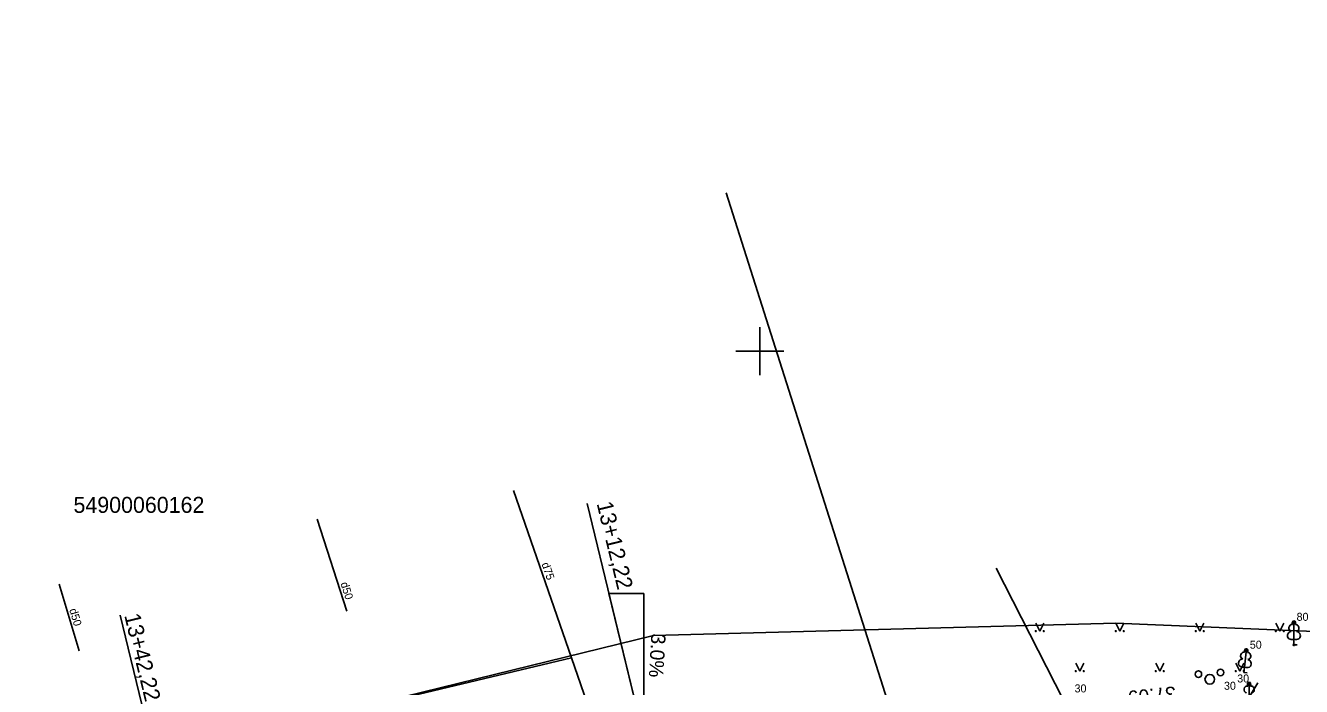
# Model space of a CAD drawing. Extents: x 469981 to 472086, y 246785 to 247785.
# Drawn here: x 470754.1 to 470833.9, y 247229 to 247270.3 of the extents above; entities that cross this region are included whole.
import ezdxf

# ---------------------------------------------------------------- set-up
doc = ezdxf.new("R2010")
doc.units = 0
for name, color, linetype in [('0_Koki_certami', 7, 'Continuous'), ('0_vertkals_cipari', 7, 'Continuous'), ('0_Virazjas', 7, 'Continuous'), ('DREN_VADP_####_####_#', 7, 'Continuous'), ('DREN_VADP_####_TKST_#', 7, 'Continuous'), ('DREN_VADP_KLKT_####_#', 7, 'Continuous'), ('DREN_VADP_KLKT_TKST_#', 7, 'Continuous'), ('GEOD_ELEM_####_####_#', 7, 'Continuous'), ('RAMI_UZMR_####_####_#', 7, 'Continuous'), ('RELJ_ELEM_####_####_#', 7, 'Continuous'), ('ROBZ_PROJ_####_####_#', 7, 'Continuous'), ('ROBZ_PROJ_####_TKST_#', 7, 'Continuous'), ('TERT_DIAM_####_TKST_#', 7, 'Continuous'), ('TERT_ELEM_####_####_#', 7, 'Continuous'), ('TERT_KOKR_####_####_#', 7, 'Continuous')]:
    doc.layers.add(name, color=color, linetype=linetype)

msp = doc.modelspace()

# ---------------------------------------------------------------- linework, layer by layer
at = {"layer": '0_Koki_certami'}
msp.add_line((470831.138, 247229.278), (470830.109, 247227.575), dxfattribs=at)
at = {"layer": '0_Virazjas'}
for p, q in [((470789.207, 247240.478), (470794.554, 247218.496)), ((470760.032, 247233.489), (470765.404, 247211.405))]:
    msp.add_line(p, q, dxfattribs=at)
msp.add_lwpolyline([(470792.75, 247234.859), (470790.575, 247234.855), (470792.763, 247225.859)], close=True, dxfattribs=at)
at = {"layer": 'DREN_VADP_####_####_#'}
for points in [[(470774.193, 247233.753), (470772.334, 247239.501)], [(470756.214, 247235.437), (470757.459, 247231.26)], [(470788.229, 247230.84), (470790.777, 247223.487), (470677.88, 247197.532)], [(470730.143, 247216.979), (470788.229, 247230.84)]]:
    msp.add_lwpolyline(points, dxfattribs=at)
at = {"layer": 'DREN_VADP_KLKT_####_#'}
msp.add_lwpolyline([(470788.229, 247230.84), (470784.609, 247241.284)], dxfattribs=at)
at = {"layer": 'GEOD_ELEM_####_####_#'}
for p, q in [((470800, 247251.5), (470800, 247250)), ((470798.5, 247250), (470800, 247250)), ((470800, 247250), (470800, 247248.5)), ((470800, 247250), (470801.5, 247250))]:
    msp.add_line(p, q, dxfattribs=at)
at = {"layer": 'RAMI_UZMR_####_####_#'}
msp.add_lwpolyline([(470560.64, 247175.144), (470793.366, 247232.231), (470822.25, 247233), (470855.497, 247231.608), (470869.75, 247235.5), (470872.288, 247238.827), (470875.523, 247240.24), (470882.387, 247236.327), (470885.36, 247235.904), (470900.348, 247222.872), (470947.872, 247208.875), (470978.25, 247197.629), (470994.287, 247200.731), (471010.572, 247199.465), (471044.448, 247201.846)], dxfattribs=at)
at = {"layer": 'RELJ_ELEM_####_####_#'}
msp.add_circle((470833.387, 247231.643), 0.05, dxfattribs=at)
at = {"layer": 'ROBZ_PROJ_####_####_#'}
for points in [[(470900.878, 247270.342), (470921.641, 247209.731), (470876.169, 247225.296), (470845.751, 247226.447), (470809.088, 247224.67), (470797.907, 247259.877)], [(470797.907, 247259.877), (470809.088, 247224.67), (470783.692, 247219.293), (470688.303, 247197.106), (470715, 247245.697)]]:
    msp.add_lwpolyline(points, dxfattribs=at)
at = {"layer": 'TERT_ELEM_####_####_#'}
for p, q in [((470817.25, 247233), (470817.5, 247232.5)), ((470817.5, 247232.5), (470817.75, 247233)), ((470822.25, 247233), (470822.5, 247232.5)), ((470822.5, 247232.5), (470822.75, 247233)), ((470827.25, 247233), (470827.5, 247232.5)), ((470827.5, 247232.5), (470827.75, 247233)), ((470832.25, 247233), (470832.5, 247232.5)), ((470832.5, 247232.5), (470832.75, 247233)), ((470833.387, 247231.99), (470833.387, 247231.643)), ((470833.387, 247231.643), (470833.587, 247231.643)), ((470819.75, 247230.5), (470820, 247230)), ((470820, 247230), (470820.25, 247230.5)), ((470824.75, 247230.5), (470825, 247230)), ((470825, 247230), (470825.25, 247230.5)), ((470829.75, 247230.5), (470830, 247230)), ((470830, 247230), (470830.25, 247230.5)), ((470830.295, 247230.257), (470830.257, 247229.912)), ((470830.257, 247229.912), (470830.456, 247229.89))]:
    msp.add_line(p, q, dxfattribs=at)
for points in [[(470833.387, 247233.143), (470833.387, 247231.99)], [(470833.477, 247232.911), (470833.476, 247232.912)], [(470830.423, 247231.403), (470830.295, 247230.257)], [(470830.486, 247231.162), (470830.485, 247231.163)], [(470830.588, 247229.301), (470830.588, 247228.148)], [(470830.677, 247229.069), (470830.676, 247229.07)]]:
    msp.add_lwpolyline(points, dxfattribs=at)
for centre, radius in [((470817.25, 247232.5), 0.028), ((470817.75, 247232.5), 0.0263), ((470822.25, 247232.5), 0.028), ((470822.75, 247232.5), 0.0263), ((470827.25, 247232.5), 0.028), ((470827.75, 247232.5), 0.0263), ((470832.25, 247232.5), 0.028), ((470832.75, 247232.5), 0.0263), ((470819.75, 247230), 0.028), ((470820.25, 247230), 0.0263), ((470824.75, 247230), 0.028), ((470825.25, 247230), 0.0263), ((470827.416, 247229.815), 0.204), ((470828.792, 247229.916), 0.207), ((470829.75, 247230), 0.028), ((470830.25, 247230), 0.0263), ((470828.13, 247229.491), 0.301)]:
    msp.add_circle(centre, radius, dxfattribs=at)
for centre, major_axis, ratio, start_param, end_param in [((470833.297, 247232.236), (0.307, 0.095), 0.814445, 1.570796, 4.752015), ((470833.259, 247232.698), (-0.039, -0.212), 0.861323, 3.141593, 6.283185), ((470833.387, 247232.993), (0, -0.15), 0.707107, 3.14537, 5.287485), ((470833.387, 247232.993), (0, -0.15), 0.707107, 0.995701, 3.137816), ((470833.477, 247232.236), (-0.307, 0.095), 0.814445, 1.531171, 4.712389), ((470833.515, 247232.698), (0.039, -0.212), 0.861323, 0, 3.141593), ((470830.246, 247230.975), (-0.062, -0.207), 0.861323, 3.141593, 6.283185), ((470830.407, 247231.254), (-0.017, -0.149), 0.707107, 3.14537, 5.287485), ((470830.406, 247231.254), (-0.017, -0.149), 0.707107, 0.995701, 3.137816), ((470830.501, 247230.946), (0.015, -0.215), 0.861323, 0, 3.141593), ((470830.233, 247230.511), (0.315, 0.061), 0.814445, 1.570796, 4.752015), ((470830.411, 247230.491), (-0.294, 0.128), 0.814445, 1.531171, 4.712389), ((470830.588, 247229.151), (0, -0.15), 0.707107, 3.14537, 5.287485), ((470830.587, 247229.151), (0, -0.15), 0.707107, 0.995701, 3.137816), ((470830.46, 247228.856), (-0.039, -0.212), 0.861323, 3.141593, 6.283185), ((470830.716, 247228.856), (0.039, -0.212), 0.861323, 0, 3.141593)]:
    msp.add_ellipse(centre, major_axis=major_axis, ratio=ratio, start_param=start_param, end_param=end_param, dxfattribs=at)
at = {"layer": 'TERT_KOKR_####_####_#'}
msp.add_lwpolyline([(470819.511, 247227.17), (470814.776, 247236.436)], dxfattribs=at)

# ---------------------------------------------------------------- texts
at = {"layer": '0_vertkals_cipari'}
msp.add_text('37.09', height=0.9, rotation=185.73163, dxfattribs=at).set_placement((470825.97, 247229.057))
at = {"layer": '0_Virazjas'}
for s, height, rotation, p in [('13+12,22', 1, 283.67202, (470789.803, 247240.476)), ('13+42,22', 1, 283.67202, (470760.281, 247233.485)), ('3.0%', 0.899, 266.55019, (470793.232, 247232.37))]:
    msp.add_text(s, height=height, rotation=rotation, dxfattribs=at).set_placement(p)
at = {"layer": 'DREN_VADP_####_TKST_#'}
for rotation, p in [(287.92547, (470773.792, 247235.481)), (286.59398, (470756.847, 247233.837))]:
    msp.add_text('d50', height=0.5, rotation=rotation, dxfattribs=at).set_placement(p)
at = {"layer": 'DREN_VADP_KLKT_TKST_#'}
msp.add_text('d75', height=0.5, rotation=289.11721, dxfattribs=at).set_placement((470786.357, 247236.7))
at = {"layer": 'ROBZ_PROJ_####_TKST_#'}
msp.add_text('54900060162', height=1, dxfattribs=at).set_placement((470757.114, 247239.889))
at = {"layer": 'TERT_DIAM_####_TKST_#'}
for s, p in [('80', (470833.553, 247233.144)), ('50', (470830.629, 247231.402)), ('30', (470819.677, 247228.669)), ('30', (470829.016, 247228.836)), ('30', (470829.843, 247229.291))]:
    msp.add_text(s, height=0.5, dxfattribs=at).set_placement(p)

doc.saveas('drawing.dxf')
